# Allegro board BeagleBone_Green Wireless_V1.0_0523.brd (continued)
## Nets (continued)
CAP_VDD_SRAM_MPU: C90.1 U5.D11(CAP_VDD_SRAM_MPU)
CLKOUT2: P2.18(EMU3) P9.41(21) R19.2 R20.1 U22.20(B1)
CLKOUT_SRC: R19.1 U5.D14(EVENT_INTR1/TCLKIN/CLKOUT2/TIME)
DDR_A0: U5.F3(DDR_A0) U12.N3(A0)
DDR_A1: U5.H1(DDR_A1) U12.P7(A1)
DDR_A2: U5.E4(DDR_A2) U12.P3(A2)
DDR_A3: U5.C3(DDR_A3) U12.N2(A3)
DDR_A4: U5.C2(DDR_A4) U12.P8(A4)
DDR_A5: U5.B1(DDR_A5) U12.P2(A5)
DDR_A6: U5.D5(DDR_A6) U12.R8(A6)
DDR_A7: U5.E2(DDR_A7) U12.R2(A7)
DDR_A8: U5.D4(DDR_A8) U12.T8(A8)
DDR_A9: U5.C1(DDR_A9) U12.R3(A9)
DDR_A10: U5.F4(DDR_A10) U12.L7(A10)
DDR_A11: U5.F2(DDR_A11) U12.R7(A11)
DDR_A12: U5.E3(DDR_A12) U12.N7(A12)
DDR_A13: U5.H3(DDR_A13) U12.T3(A13)
DDR_A14: U5.H4(DDR_A14) U12.T7(A14)
DDR_A15: U5.D3(DDR_A15) U12.M7(A15)
DDR_BA0: U5.C4(DDR_BA0) U12.M2(BA0)
DDR_BA1: U5.E1(DDR_BA1) U12.N8(BA1)
DDR_BA2: U5.B3(DDR_BA2) U12.M3(BA2)
DDR_CASN: U5.F1(DDR_CASN) U12.K3(CASN)
DDR_CKE: R96.2 U5.G3(DDR_CKE) U12.K9(CKE)
DDR_CLK: U5.D2(DDR_CK) U12.J7(CK)
DDR_CLKN: U5.D1(DDR_NCK) U12.K7(CKN)
DDR_CSN: U5.H2(DDR_CSN0) U12.L2(CSN)
DDR_D0: U5.M3(DDR_D0) U12.E3(DQ0)
DDR_D1: U5.M4(DDR_D1) U12.F7(DQ1)
DDR_D2: U5.N1(DDR_D2) U12.F2(DQ2)
DDR_D3: U5.N2(DDR_D3) U12.F8(DQ3)
DDR_D4: U5.N3(DDR_D4) U12.H3(DQ4)
DDR_D5: U5.N4(DDR_D5) U12.H8(DQ5)
DDR_D6: U5.P3(DDR_D6) U12.G2(DQ6)
DDR_D7: U5.P4(DDR_D7) U12.H7(DQ7)
DDR_D8: U5.J1(DDR_D8) U12.D7(DQ8)
DDR_D9: U5.K1(DDR_D9) U12.C3(DQ9)
DDR_D10: U5.K2(DDR_D10) U12.C8(DQ10)
DDR_D11: U5.K3(DDR_D11) U12.C2(DQ11)
DDR_D12: U5.K4(DDR_D12) U12.A7(DQ12)
DDR_D13: U5.L3(DDR_D13) U12.A2(DQ13)
DDR_D14: U5.L4(DDR_D14) U12.B8(DQ14)
DDR_D15: U5.M1(DDR_D15) U12.A3(DQ15)
DDR_DQM0: U5.M2(DDR_DQM0) U12.E7(LDM)
DDR_DQM1: U5.J2(DDR_DQM1) U12.D3(UDM)
DDR_DQS0: U5.P1(DDR_DQS0) U12.F3(LDQS)
DDR_DQS1: U5.L1(DDR_DQS1) U12.C7(UDQS)
DDR_DQSN0: U5.P2(DDR_DQSN0) U12.G3(LDQSN)
DDR_DQSN1: U5.L2(DDR_DQSN1) U12.B7(UDQSN)
DDR_ODT: U5.G1(DDR_ODT) U12.K1(ODT)
DDR_RASN: U5.G4(DDR_RASN) U12.J3(RASN)
DDR_RESETN: R97.2 U5.G2(DDR_RESETN) U12.T2(RESET#)
DDR_VREF: C28.1 C123.1 C124.1 R98.2 R100.1 U5.J4(VREFSSTL) U12.H1(VREF_DQ) U12.M8(VREF_CA)
DDR_VTP: R22.2 U5.J3(DDR_VTP)
DDR_WEN: U5.B2(DDR_WEN) U12.L3(WEN)
EHRPWM1A: P9.14(32) U5.U14(GPMC_A2/GMII2_TXD3/RGMII2_TD3/M)
EHRPWM1B: P9.16(33) U5.T14(GPMC_A3/GMII2_TXD2/RGMII2_TD2/M)
EHRPWM2A: P8.19(10) U5.U10(GPMC_AD8/LCD_DATA23/MMC1_DAT0/M)
EHRPWM2B: P8.13(7) U5.T10(GPMC_AD9/LCD_DATA22/MMC1_DAT1/M)
EMMC_RSTN: R111.2 R162.2 U13.K5(R\S\T\)
EMMC_VCCI: C125.1 U13.C2(VCCI)
ENZ_KALDO_1P8V: R54.2 U5.B4(ENZ_KALDO_1P8V)
GPIO0_7: P9.42(46) R50.1 R51.1
GPIO0_7SRC: R50.2 U5.C18(ECAP0_IN_PWM0_OUT/UART3_TXD/SPI)
GPIO0_26: P8.14(32) R187.2 R189.1 U5.T11(GPMC_AD10/LCD_DATA21/MMC1_DAT2/)
GPIO0_27: P8.17(9) U5.U12(GPMC_AD11/LCD_DATA20/MMC1_DAT3/) U22.18(B2)
GPIO1_12: P8.12(31) R206.1 U5.T12(GPMC_AD12/LCD_DATA19/MMC1_DAT4/)
GPIO1_13: P8.11(6) R205.1 U5.R12(GPMC_AD13/LCD_DATA18/MMC1_DAT5/)
GPIO1_14: P8.16(33) R204.1 U5.V13(GPMC_AD14/LCD_DATA17/MMC1_DAT6/)
GPIO1_15: P8.15(8) R203.1 U5.U13(GPMC_AD15/LCD_DATA16/MMC1_DAT7/)
GPIO1_16: P9.15(8) R160.2
GPIO1_17: P9.23(12) U5.V14(GPMC_A1/GMII2_RXDV/RGMII2_RCTL/)
GPIO1_28: P9.12(31) R188.2 R190.1 U5.U18(GPMC_BE1N/GMII2_COL/GPMC_CSN6/M)
GPIO1_29: P8.26(38) R198.1 U5.V6(GPMC_CSN0/GPIO1_29)
GPIO2_0: R161.2 R208.1
GPIO2_1: P8.18(34) R207.1 U5.V12(GPMC_CLK/LCD_MEM_CLK/GPMC_WAIT1)
GPIO3_18: R51.2 U5.B12(MCASP0_ACLKR/EQEP0A_IN/MCASP0_A)
GPIO3_19: P9.27(14) U5.C13(MCASP0_FSR/EQEP0B_IN/MCASP0_AXR)
GPIO3_20: R20.2 U5.D13(MCASP0_AXR1/EQEP0_INDEX//MCASP1)
GPIO3_21: P9.25(13) R167.2 U5.A14(MCASP0_AHCLKX/EQEP0_STROBE/MCAS)
HDMI_INT: R169.1 R170.1 U5.U16(GPMC_A9/GMII2_RXD2/RGMII2_RD2/M)
HDMICLK_DISN: U5.V17(GPMC_A11/GMII2_RXD0/RGMII2_RD0/) Y4.1(OE)
HUB_AVDD: C181.1 C182.1 C185.1 C186.2 C187.1 C188.1 L15.2 R219.1 R220.1 R225.2 U23.5(AVDD#5) U23.9(AVDD#9) U23.14(AVDD#14) U23.28(V33)
HUB_DM1: D11.1 J8.A2(DM_T) U23.3(DM1)
HUB_DM2: D14.2 J8.B2(DM_B) U23.6(DM2)
HUB_DM3: D17.1 J9.A2(DM_T) U23.12(DM3)
HUB_DM4: D20.2 J9.B2(DM_B) U23.15(DM4)
HUB_DP1: D10.1 J8.A3(DP_T) U23.4(DP1)
HUB_DP2: D13.2 J8.B3(DP_B) U23.7(DP2)
HUB_DP3: D16.1 J9.A3(DP_T) U23.13(DP3)
HUB_DP4: D19.2 J9.B3(DP_B) U23.16(DP4)
HUB_RESET#: C199.1 R227.1 R228.2 U23.17(RESET#)
HUB_VBUS: C190.1 C192.1 C194.1 C196.1 C198.1 FB8.2 L17.2 L18.2 L19.2 L20.2 U24.1(OUT)
I2C0_SCL: R3.2 U2.28(SCL) U5.C16(I2C0_SCL/TIMER7/UART2_RTSN/ECAP) U7.1(SCL)
I2C0_SDA: R4.2 U2.27(SDA) U5.C17(I2C0_SDA/TIMER4/UART2_CTSN/ECAP) U7.3(SDA)
I2C1_SCL: P9.17(9) U5.A16(SPI0_CS0/MMC2_SDWP/I2C1_SCL/EHR)
I2C1_SDA: P9.18(34) U5.B16(SPI0_D1/MMC1_SDWP/I2C1_SDA/EHRP)
I2C2_SCL: C202.1 J4.1 P9.19(10) U5.D17(UART1_RTSN/TIMER5/DCAN0_RX/I2C2)
I2C2_SDA: C203.1 J4.2 P9.20(35) U5.D18(UART1_CTSN/TIMER6/DCAN0_TX/I2C2)
JTAG_EMU0: P2.13(EMU0) R23.2 U5.C14(EMU0/GPIO3_7)
JTAG_EMU1: P2.14(EMU1) R24.2 U5.B14(EMU1/GPIO3_8)
JTAG_TCK: P2.9(TCKRTN) P2.11(TCK) U5.A12(TCK)
JTAG_TDI: P2.3(TDI) U5.B11(TDI)
JTAG_TDO: P2.7(TDO) U5.A11(TDO)
JTAG_TMS: P2.1(TMS) U5.C11(TMS)
JTAG_TRSTN: P2.2(TRSTN) R25.1 U5.B10(NTRST)
LCD_DATA0: P8.45(23) R70.2 R95.1 U5.R1(LCD_DATA0/GPMC_A0//EHRPWM2A//PR)
LCD_DATA1: P8.46(48) R69.2 R94.1 U5.R2(LCD_DATA1/GPMC_A1//EHRPWM2B//PR)
LCD_DATA2: P8.43(22) R68.2 R75.1 R93.1 U5.R3(LCD_DATA2/GPMC_A2//EHRPWM2_TRIP)
LCD_DATA3: P8.44(47) R67.2 R92.1 U5.R4(LCD_DATA3/GPMC_A3//EHRPWM2_SYNC)
LCD_DATA4: P8.41(21) R66.2 R91.1 U5.T1(LCD_DATA4/GPMC_A4//EQEP2A_IN//P)
LCD_DATA5: P8.42(46) R65.2 R90.1 U5.T2(LCD_DATA5/GPMC_A5//EQEP2B_IN//P)
LCD_DATA6: P8.39(20) R64.2 R89.1 U5.T3(LCD_DATA6/GPMC_A6/PR1_EDIO_DATA)
LCD_DATA7: P8.40(45) R63.2 R88.1 U5.T4(LCD_DATA7/GPMC_A7/PR1_EDIO_DATA)
LCD_DATA8: P8.37(19) R62.2 R87.1 U5.U1(LCD_DATA8/GPMC_A12/EHRPWM1_TRIP)
LCD_DATA9: P8.38(44) R61.2 R86.1 U5.U2(LCD_DATA9/GPMC_A13/EHRPWM1_SYNC)
LCD_DATA10: P8.36(43) R60.2 R85.1 U5.U3(LCD_DATA10/GPMC_A14/EHRPWM1A/MC)
LCD_DATA11: P8.34(42) R59.2 R84.1 U5.U4(LCD_DATA11/GPMC_A15/EHRPWM1B/MC)
LCD_DATA12: P8.35(18) R58.2 R83.1 U5.V2(LCD_DATA12/GPMC_A16/EQEP1A_IN/M)
LCD_DATA13: P8.33(17) R57.2 R82.1 U5.V3(LCD_DATA13/GPMC_A17/EQEP1B_IN/M)
LCD_DATA14: P8.31(16) R56.2 R81.1 U5.V4(LCD_DATA14/GPMC_A18/EQEP1_INDEX)
LCD_DATA15: P8.32(41) R55.2 R80.1 U5.T5(LCD_DATA15/GPMC_A19/EQEP1_STROB)
LCD_DE: P8.30(40) R48.2
LCD_HSYNC: P8.29(15) R47.2
LCD_PCLK: P8.28(39) R45.2
LCD_VSYNC: P8.27(14) R46.2
LCDDE: R48.1 U5.R6(LCD_AC_BIAS_EN/GPMC_A11//PR1_ED)
LCDPCLK: R45.1 U5.V5(LCD_PCLK/GPMC_A10//PR1_EDIO_DAT)
LCDVHYNC: R47.1 U5.R5(LCD_HSYNC/GPMC_A9//PR1_EDIO_DAT)
LCDVSYNC: R46.1 U5.U5(LCD_VSYNC/GPMC_A8//PR1_EDIO_DAT)
LDO_PGOOD: U2.46(LDO_PGOOD) U5.B5(RTC_PORZN)
LEDAA: D2.2(A) R72.2
LEDAC: D2.1(C) Q1.6(3)
LEDBA: D3.2(A) R73.2
LEDBC: D3.1(C) Q1.3
LEDCA: D4.2(A) R74.2
LEDCC: D4.1(C) Q2.6(3)
LEDDA: D5.2(A) R71.2
LEDDC: D5.1(C) Q2.3
MMC0_CD: P2.19(EMU4) P10.10(CD) R157.1 U5.C15(SPI0_CS1/UART3_RXD/ECAP1_IN_PWM)
MMC0_CLKO: P10.5(CLOCK) R152.2 U5.G17(MMC0_CLK/GPMC_A24/UART3_CTSN/UA)
MMC0_CMD: P10.3(CMD) R151.2 U5.G18(MMC0_CMD/GPMC_A25/UART3_RTSN/UA)
MMC0_DAT0: P10.7(DAT0) R153.2 U5.G16(MMC0_DAT0/GPMC_A23/UART5_RTSN/U)
MMC0_DAT1: P10.8(DAT1) R154.2 U5.G15(MMC0_DAT1/GPMC_A22/UART5_CTSN/U)
MMC0_DAT2: P10.1(DAT2) R150.2 U5.F18(MMC0_DAT2/GPMC_A21/UART4_RTSN/T)
MMC0_DAT3: P10.2(CD/DAT3) R155.2 U5.F17(MMC0_DAT3/GPMC_A20/UART4_CTSN/T)
MMC1_CLK: P8.21(11) R110.2 U5.U9(GPMC_CSN1/GPMC_CLK/MMC1_CLK/PRT) U13.M6(CLK)
MMC1_CMD: P8.20(35) R109.2 U5.V9(GPMC_CSN2/GPMC_BE1N/MMC1_CMD/PR) U13.M5(CMD)
MMC1_DAT0: P8.25(13) R101.2 U5.U7(GPMC_AD0/MMC1_DAT0//////GPIO1_0) U13.A3(DAT0)
MMC1_DAT1: P8.24(37) R102.2 U5.V7(GPMC_AD1/MMC1_DAT1//////GPIO1_1) U13.A4(DAT1)
MMC1_DAT2: P8.5(3) R103.2 U5.R8(GPMC_AD2/MMC1_DAT2//////GPIO1_2) U13.A5(DAT2)
MMC1_DAT3: P8.6(28) R104.2 U5.T8(GPMC_AD3/MMC1_DAT3//////GPIO1_3) U13.B2(DAT3)
MMC1_DAT4: P8.23(12) R105.2 U5.U8(GPMC_AD4/MMC1_DAT4//////GPIO1_4) U13.B3(DAT4)
MMC1_DAT5: P8.22(36) R106.2 U5.V8(GPMC_AD5/MMC1_DAT5//////GPIO1_5) U13.B4(DAT5)
MMC1_DAT6: P8.3(2) R107.2 U5.R9(GPMC_AD6/MMC1_DAT6//////GPIO1_6) U13.B5(DAT6)
MMC1_DAT7: P8.4(27) R108.2 U5.T9(GPMC_AD7/MMC1_DAT7//////GPIO1_7) U13.B6(DAT7)
OSC0_IN: R234.1 U5.V10(OSC0_IN) U17.5(MOD OUT)
OSC0_OUT: R235.1 U5.U11(OSC0_OUT)
OSC1_IN: C21.2 U5.A6(OSC1_IN) Y1.1
OSC1_OUT: C22.2 U5.A4(OSC1_OUT) Y1.4
OVCUR1#: R224.1 U23.25(OVCUR1#)
P_BYPASS: C4.2 U2.47(BYPASS)
P_INT_LDO: C3.2 U2.48(INT_LDO)
P_L1: L1.1 U2.20(L1)
P_L2: L2.1 U2.23(L2)
P_L3: L3.1 U2.31(L3)
PGANG: D6.1(C) R220.2 U23.23(PGANG)
PMIC_INT: R1.2 U2.45(INT) U5.B18(NNMI)
PMIC_PGOOD: U2.26(PGOOD) U5.B15(PORZN) U16.2(A)
PMIC_POWR_EN: U2.9(PWR_EN) U5.C6(PMIC_POWER_EN)
PROC_A15: R18.1 U5.A15(EVENT_INTR0/TIMER4/CLKOUT1/SPI1)
PSELF: R225.1 R226.2 U23.22(PSELF)
PWR_BUT: P9.9(5) S3.2(B1) S3.4(B2) U2.25(PB_IN)
PWR_LEDR: D1.1(C) R12.2
SLOW_CLK: R213.1 U22.1(A1)
SPI1_CS0: P9.28(39) R236.1 U5.C12(MCASP0_AHCLKR/EHRPWM0_SYNCI_O/M)
SPI1_D0: P9.29(15) R238.1 U5.B13(MCASP0_FSX/EHRPWM0B//SPI1_D0/MM)
SPI1_D1: P9.30(40) R237.1 U5.D12(MCASP0_AXR0/EHRPWM0_TRIPZONE_IN)
SPI1_SCLK: P9.31(16) R239.1 U5.A13(MCASP0_ACLKX/EHRPWM0A//SPI1_SCL)
SYS_5V: C7.2 C8.2 C10.2 C13.2 C180.2 L13.1 L16.2 P9.7(4) P9.8(29) R71.1 R72.1 R73.1 R74.1 R227.2 U2.2(VINLDO) U2.7(SYS1) U2.8(SYS2) U2.21(VIN_DCDC1) U2.22(VIN_DCDC2) U2.32(VIN_DCDC3) U2.39(LDO3_IN) U2.42(LDO4_IN) U20.7(AVIN) U20.8(PVIN)
SYS_RESETN: C24.1 C30.1 P2.15(SRST) P9.10(30) R14.2 S1.2(B1) S1.4(B2) U5.A10(NRESET_INOUT) U16.4(Y)
TESTOUT: TP3.1(TP) U5.A3(TESTOUT)
TIMER4: P8.7(4) U5.R7(GPMC_ADVN_ALE/TIMER4/GPIO2_2)
TIMER5: P8.9(5) U5.T6(GPMC_BE0N_CLE/TIMER5/GPIO2_5)
TIMER6: P8.10(30) U5.U6(GPMC_WEN/TIMER6/GPIO2_4)
TIMER7: P8.8(29) U5.T7(GPMC_OEN_REN/TIMER7/EMU4/GPIO2_)
U5_R13: R160.1 U5.R13(GPMC_A0/GMII2_TXEN/RGMII2_TCTL/)
U5_T13: R161.1 U5.T13(GPMC_CSN3/MMC2_CMD/PR1_MDIO_DAT)
UART0_RX: U5.E15(UART0_RXD/SPI1_CS0/DCAN0_TX/I2C) U15.6(1Y)
UART0_TX: U5.E16(UART0_TXD/SPI1_CS1/DCAN0_RX/I2C) U15.5(2A)
UART1_RXD: P9.26(38) U5.D16(UART1_RXD/MMC1_SDWP/DCAN1_TX/I2)
UART1_TXD: P9.24(37) U5.D15(UART1_TXD/MMC2_SDWP/DCAN1_RX/I2)
UART2_RXD: C204.1 J5.1 P9.22(36) U5.A17(SPI0_SCLK/UART2_RXD/I2C2_SDA/EH)
UART2_TXD: C205.1 J5.2 P9.21(11) U5.B17(SPI0_D0/UART2_TXD/I2C2_SCL/EHRP)
UART3_CTSN: R200.1 R210.1 U5.M17(MDIO_DATA/TIMER6/UART5_RXD/UART)
UART3_RTSN: R199.1 R209.1 U5.M18(MDIO_CLK/TIMER5/UART5_TXD/UART3)
UART3_RXD: U5.L17(GMII1_RXD3/UART3_RXD/RGMII1_RD3) U21.14(B6)
UART3_TXD: U5.L16(GMII1_RXD2/UART3_TXD/RGMII1_RD2) U21.15(B5)
UART4_RXD: P9.11(6) U5.T17(GPMC_WAIT0/GM112_CRS/GPMC_CSN4/)
UART4_TXD: P9.13(7) U5.U17(GPMC_WPN/GMII2_RXERR/GPMC_CSN5/)
USB0_DM: D21.2 P4.2(D-) U5.N18(USB0_DM)
USB0_DP: D22.2 P4.3(D+) U5.N17(USB0_DP)
USB0_ID: D23.2 P4.4(ID) U5.P16(USB0_ID)
USB1_DM: U5.R18(USB1_DM) U23.1(DM0)
USB1_DP: U5.R17(USB1_DP) U23.2(DP0)
USB1_DRVVBUS: R221.2 U5.F15(USB1_DRVVBUS/GPIO3_13) U24.4(EN)
USB1_ID: R49.2 U5.P17(USB1_ID)
USB1_OCN: R223.1 R224.2 U5.T16(GPMC_A10/GMII2_RXD1/RGMII2_RD1/) U24.3(NFAULT)
USB1_VBUS: FB8.1 U5.T18(USB1_VBUS)
USB_DC: C1.2 C36.1 C197.1 D24.2 P4.1(VB) R159.1 R168.1 U2.12(USB) U24.6(IN)
USR0: Q1.2(5) R76.1 U5.V15(GPMC_A5/GMII2_TXD0/RGMII2_TD0/R)
USR1: Q1.5 R77.1 U5.U15(GPMC_A6/GMII2_TXCLK/RGMII2_TCLK)
USR2: Q2.2(5) R78.1 U5.T15(GPMC_A7/GMII2_RXCLK/RGMII2_RCLK)
USR3: Q2.5 R79.1 U5.V16(GPMC_A8/GMII2_RXD3/RGMII2_RD3/M)
VDCDC1: L1.2 R6.1 U2.19(VDCDC1)
VIO: R7.2 U2.18(VIO) U16.5(VCC)
VLDO1: R5.1 R7.1 R8.1 U2.3(VLDO1)
VREFP_ADC: C31.1 C32.1 C33.1 R27.2 U5.B9(VREFP)
VRTC: C16.1 C105.1 R5.2 R26.1 U5.D7(VDDS_RTC)
WAKEUP: R26.2 U2.13(WAKEUP) U5.C5(EXT_WAKEUP)
WL_EN: Q4.1(GATE) R187.1 U18.40(WLAN_EN_SOC)
WL_IRQ: R176.1 U22.3(A2)
WL_SDIO_CLK: R182.1 R195.2 U22.8(A7)
WL_SDIO_CMD: R181.1 R196.2 U22.9(A8)
WL_SDIO_D0: R180.1 R194.2 U22.7(A6)
WL_SDIO_D1: R179.1 R193.2 U22.6(A5)
WL_SDIO_D2: R178.1 R192.2 U22.5(A4)
WL_SDIO_D3: R177.1 R191.2 U22.4(A3)
WP: R156.2 TP4.1(TP) U7.5(WP)
XDMA_EVENT_INTR0: P2.17(EMU2) R18.2
XTAL1: C183.1 U23.10(XTAL1) Y5.1
XTAL2: C184.1 U23.11(XTAL2) Y5.3
ZQ: R99.1 U12.L8(ZQ)
N21769115: R75.2 S2.1(A1) S2.3(A2)
N22155575: R159.2 U5.P15(USB0_VBUS)
N22248684: R167.1 Y4.3(CLK)
N22287501: R162.1 U3.4(Y)
N22287555: U3.2(A) U5.R14(GPMC_A4/GMII2_TXD1/RGMII2_TD1/R)
N22420400: TP5.1(TP) U2.4(BAT1) U2.5(BAT2)
N22420444: TP6.1(TP) U2.6(BAT_SENSE)
N22420447: TP7.1(TP) U2.11(TS)
N22488252: TP9.1(TP) U5.E17(UART0_RTSN/UART4_TXD/DCAN1_RX/I)
N22648410: C25.1 R17.1 R234.2 U17.1(XIN/CXIN) Y2.2
N22648422: C26.1 R17.2 R235.2 U17.2(CKOUT) Y2.1
N22649826: R171.2 U17.3(SSON)
N22650321: R172.2 R174.1 U17.6(ADS0)
N22650344: R173.1 R175.2 U17.7(ADS1)
N22699644: R176.2 R233.2 U18.14(WLAN_IRQ)
N22699649: R177.2 U18.13(WL_SDIO_D3)
N22699658: R178.2 U18.12(WL_SDIO_D2)
N22699663: R179.2 U18.11(WL_SDIO_D1)
N22699668: R180.2 U18.10(WL_SDIO_D0)
N22699673: R181.2 U18.6(WL_SDIO_CMD)
N22699720: R182.2 U18.8(WL_SDIO_CLK)
N22699759: R183.2 U18.50(BT_HCI_RTS)
N22699762: R184.2 U18.51(BT_HCI_CTS)
N22699765: R185.2 U18.52(BT_HCI_TX)
N22699768: R186.2 U18.53(BT_HCI_RX)
N22705626: OSC1.3(OUT) R213.2 U18.36(EXT_32K)
N22705631: C167.1 L4.1 OSC1.1(EN) OSC1.4(VDD)
N22709787: TP22.1(TP) U18.43(BT_UART_DBG)
N22709790: TP23.1(TP) U18.42(WL_UART_DBG)
N22711010: C171.1 C200.1 L7.2 L21.2 U18.32(2G4_ANT1_WB)
N22711020: C171.2 J6.1(CENTER) L8.2
N22712983: C172.1 L9.2 U18.18(2G4_ANT2_W)
N22712987: C172.2 J7.1(CENTER) L10.2
N22724780: R197.1 R198.2 U21.10(OE) U22.10(OE)
N22729983: R203.2 U22.17(B3)
N22729986: R204.2 U22.16(B4)
N22729989: R205.2 U22.15(B5)
N22729992: R206.2 U22.14(B6)
N22729995: R207.2 U22.13(B7)
N22729998: R208.2 U22.12(B8)
N22732227: TP14.1(TP) U18.27(GPIO_1)
N22732237: TP15.1(TP) U18.26(GPIO_2)
N22732240: TP16.1(TP) U18.25(GPIO_4)
N22732294: TP17.1(TP) U18.2(GPIO11)
N22732297: TP18.1(TP) U18.3(GPIO9)
N22732316: TP19.1(TP) U18.4(GPIO10)
N22732319: TP20.1(TP) U18.5(GPIO12)
N22732977: C177.2 L13.2 U19.5(EN) U19.7(AVIN) U19.8(PVIN)
N22733304: L11.1 U19.2(SW)
N22733307: R214.2 R215.1 U19.4(FB)
N22764895: L15.1 U23.21(DVDD)
N22765441: L16.1 U23.27(V5)
N22766342: R218.1 U23.8(RREF)
N22767849: TP24.1(TP) U23.26(SDA)
N22767859: TP25.1(TP) U23.18(TEST/SCL)
N22768480: D6.2(A) R219.2
N22769591: C189.1 D9.1 J8.A1(VBUS_T) L19.1
N22769632: C191.1 D12.2 J8.B1(VBUS_B) L20.1
N22770199: C193.1 D15.1 J9.A1(VBUS_T) L17.1
N22770224: C195.1 D18.2 J9.B1(VBUS_B) L18.1
N22776606: R222.2 U24.2(ILIM)
N22780216: D7.2(A) R229.2
N22783783: D8.2(A) R230.2
N22784813: ANT.1(FEED) C200.2 L22.2
N22805505: D7.1(C) Q3.3(DRAIN)
N22805508: D8.1(C) Q4.3(DRAIN)
N22816281: J4.3 R231.1
N22816655: J5.3 R232.1
N22868112: R216.2 R217.1 U20.4(FB)
N22868125: L12.1 U20.2(SW)
N22871921: R200.2 U21.12(B8)
N22871924: R199.2 U21.13(B7)
N22888492: R236.2 U21.16(B4)
N22888495: R239.2 U21.20(B1)
N22888517: R238.2 U21.18(B2)
N22888520: R237.2 U21.17(B3)

Pads without a net: J1 2 3 6; NOREF 1; NOREF#3 1; NOREF#9 1; NOREF#10 1; NOREF#12 1; NOREF#18 1; NOREF#26 1; NOREF#34 1; NOREF#35 1; NOREF#36 1; NOREF#37 1; NOREF#38 1; NOREF#39 1; NOREF#40 1; P2 6; U2 14 15 16 17 33 34 35 36 37 38 44; U3 1; U5 E18 F16 H16 H17 H18 J15 J16 J17 J18 K15 K16 K17 K18 L15 L18 M5 M15 M16 P18; U12 J1 J9 L1 L9; U13 A1 A2 A6 A7 A8 A9 A10 A11 A12 A13 A14 B1 B7 B8 B9 B10 B11 B12 B13 B14 C1 C3 C5 C7 C8 C9 C10 C11 C12 C13 C14 D1 D2 D3 D4 D12 D13 D14 E1 E2 E3 E5 E8 E9 E10 E12 E13 E14 F1 F2 F3 F10 F12 F13 F14 G1 G2 G3 G10 G12 G13 G14 H1 H2 H3 H5 H12 H13 H14 J1 J2 J3 J5 J12 J13 J14 K1 K2 K3 K6 K7 K10 K12 K13 K14 L1 L2 L3 L12 L13 L14 M1 M2 M3 M7 M8 M9 M10 M11 M12 M13 M14 N1 N3 N6 N7 N8 N9 N10 N11 N12 N13 N14 P1 P2 P7 P8 P9 P10 P11 P12 P13 P14; U16 1; U18 21 22 62; U23 19 20 24; Y1 2 3

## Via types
v1: diameter 0.457, hole 0.203, TOP to BOTTOM, 923 vias
v2: diameter 0.559, hole 0.305, TOP to BOTTOM, 34 vias
v3: diameter 0.61, hole 0.305, TOP to BOTTOM, 18 vias

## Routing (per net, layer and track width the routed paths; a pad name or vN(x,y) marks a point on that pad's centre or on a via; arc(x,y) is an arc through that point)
DGND: length 587.9
  TOP w0.076: 27.73,110.05 27.88,110.05 27.89,110.04 28.23,110.04 28.49,109.79 U13.N2
  TOP w0.178: U13.N5 U13.P4
  TOP w0.191: 40.36,102.72 40.13,102.72 39.37,103.48 36.45,103.48 36.2,103.23 ; v1(37.06,102.31) 37.06,102.44
  TOP w0.203: v1(27.41,110.21) 27.57,110.05 27.73,110.05 ; U13.H10 30.99,105.51 31.24,105.26 v1(31.24,105.18) ; U13.P4 26.98,108.79 v1(26.49,109.27) ; v1(31.19,108.81) 31.19,108.59 31.34,108.43 U13.G5 ; U2.30 25.85,80.17 25.65,80.37 v2(25.27,80.37) ; U13.P6 27.57,107.79 v1(27.43,107.65) ; U2.41 v1(24.86,84.75) ; U13.C4 v1(32.99,108.29) ; U13.K8 v1(29.46,106.79) ; v1(32.99,107.11) 32.67,107.11 U13.E7
  TOP w0.254: U5.V1 53.92,101.14 v1(53.92,101.78) ; v1(67.7,93.89) U12.D8 ; U5.F8 v1(47.92,91.94) U5.G9 ; v1(68.5,85.09) U12.P9 ; U12.G9 v1(68.5,91.49) U12.F9 ; U5.N10 v1(46.32,97.54) U5.N11 ; v1(67.7,93.09) U12.E8 ; U5.G8 v1(47.92,92.74) U5.H9 ; U5.K7 U5.J7 v1(49.52,93.54) ; U5.H10 v1(46.32,93.54) U5.J10 ; v1(68.5,83.49) U12.T9 ; U5.L13 v1(44.72,95.94) U5.L12 ; v1(46.32,95.14) U5.K10 ; v1(46.32,95.14) U5.K11 ; v1(46.32,95.14) U5.L10 ; v1(61.3,85.09) U12.P1 ; v1(68.5,86.69) U12.M9 ; v1(44.72,92.74) U5.H12 ; v1(61.3,86.69) U12.M1 ; U12.D1 v1(62.1,93.09) U12.E2 ; v1(48.72,93.54) U5.J8 ; U12.G1 60.71,92.08 60.71,92.43 61.09,92.81 61.58,92.81 U12.E1 v1(62.1,92.29) ; v1(61.3,83.49) U12.T1 ; U5.M9 v1(47.92,96.74) U5.M8 ; v1(48.72,92.74) U5.H8 ; U12.A9 v1(68.5,95.49) U12.B9 ; v1(47.92,95.14) U5.K9 ; U5.M14 v1(43.12,96.74) U5.N14 ; U5.M6 v1(49.52,95.94) U5.M7 ; v1(44.72,91.94) U5.G12 45.28,92.18 45.76,92.18 U5.G11 ; v1(20.8,97.79) 20.32,97.31 R218.2 ; v1(62.1,89.09) U12.J2 ; U5.J6 v1(50.32,93.54) U5.H6 ; v1(67.7,89.09) U12.J8 ; v1(61.3,95.49) U12.B1 ; U5.M12 v1(45.52,95.94) U5.L11 ; U5.H7 v1(49.52,92.74) ; v1(46.32,96.74) U5.M10 ; U5.J11 v1(45.52,93.54) ; v1(47.92,93.54) U5.J9 ; v1(62.9,95.49) U12.B3 ; U5.A1 v1(53.92,86.84) ; U5.A18 v1(39.92,87.13) ; v1(49.52,97.54) U5.N7 ; v1(67.7,91.49) U12.G8
  TOP w0.305: v1(55.27,113.37) 55,113.1 U21.11 ; S1.3 9.42,115.16 ; 9.42,115.16 S1.1 ; 9.42,115.16 9.63,115.37 v1(9.8,115.37) ; S3.3 S3.1 9.5,110.97 9.86,111.33 10.31,111.33 v1(10.37,111.27) ; R12.1 v1(7.32,106.12)
  TOP w0.381: v1(33.55,96.27) 33.27,96.55 C159.2 ; D14.1 v1(19.61,99.67) ; R210.2 52.93,112.73 v1(53.52,113.31) ; C183.2 19.2,96.11 Y5.4 18.97,96.34 18.97,97 18.49,97.49 17.09,97.49 16.66,97.05 16.66,95.4 17.44,94.63 Y5.2 17.59,94.1 18.06,93.62 19.56,93.62 19.6,93.67 19.64,93.67 19.85,93.87 19.85,93.91 19.94,94.01 v1(19.94,94.23) 19.94,94.59 20.19,94.84 C184.2 ; 65.26,108.85 U18.G23 ; C186.1 20.4,92.99 20.4,93.34 20.73,93.68 v1(21.67,93.68) ; C24.2 35.05,72.24 v1(35.69,71.6) 36.07,71.98 C30.2 ; R25.2 37.78,74.21 37.46,73.89 v1(37.46,73.7) ; v1(21.67,86.08) 21.59,86.08 20.7,86.97 D16.2 ; R81.2 49.23,108.89 v3(49.68,108.43) 50.11,108.86 R209.2 ; Q2.1 18.02,108.78 17.81,108.99 v1(17.32,108.99) ; D20.1 v1(16.28,86.97) ; 23.37,108.18 R77.2 23.11,109.58 22.73,109.96 22.73,110.46 v1(22.61,110.59) 22.1,110.59 21.99,110.48 Q1.4 ; Q2.4 19.32,109.76 19.48,109.6 19.84,109.6 v1(19.96,109.47) 20.34,109.09 v1(20.34,109.05) 20.44,109.05 20.69,108.8 Q1.1 ; D17.2 D19.1 v1(18.41,86.18) ; v1(31.5,92.89) 31.11,92.89 31.06,92.94 R226.1 ; 76.2,81.13 v1(76.2,81.18) 76.71,80.67 J4.4 78.9,80.67 v1(79.48,80.09) ; R85.2 53.7,105.14 53.29,105.55 53.29,105.64 v1(53.26,105.66) ; v1(23.49,86.46) 22.86,85.83 22.86,85.45 ; v1(37.46,76.3) 37.46,76.05 C29.2 ; v1(57.94,100.28) 57.94,100.97 R91.2 ; U18.61 62.3,103.6 v1(62.31,103.61) ; Y4.2 v1(32.63,99.68) ; D10.2 v1(19.63,100.56) ; 52.81,105.21 v1(53.26,105.66) ; 52.81,105.21 R83.2 ; 52.81,105.21 52.5,105.51 C175.1 53.09,105.84 v1(53.26,105.66) ; R78.2 R79.2 21.97,105.23 v1(22.48,104.72) ; v1(72.52,80.82) 73.36,80.82 L9.1 ; v1(50.29,105.21) 50.29,105.16 R82.2 ; L10.1 v1(73.53,76.94) ; L21.1 75.62,113.46 76.02,113.46 76.02,113.41 ; v1(47.75,77.71) R165.2 ; 32.77,92.05 v1(31.8,92.05) ; 57.91,77.93 57.89,77.95 C96.1 C155.1 57.02,76.81 57.12,76.81 v1(57.4,76.53) ; 12.2,111.03 12.19,111.04 v1(12.17,111.04) ; R86.2 v1(56.13,105.18) ; D11.2 v1(19.47,101.83) ; U18.1 60.8,100.43 v1(60.6,100.23) ; U16.3 32.28,74.81 v1(32,75.08) ; C18.2 v1(19.68,84.68) ; L22.1 v1(76.58,114.07) 76.58,114.1 ; R90.2 58.04,102.97 57.66,102.59 v1(57.53,102.59) 57.15,102.97 R87.2 ; D13.1 v1(19.71,98.4)
  TOP w0.889: 7.98,91.9 J8.S3 ; J8.S3 10.31,89.57 ; J8.S3 7.98,89.57 ; J8.S3 10.31,91.9 ; 11.26,94.4 J8.B4 ; J8.B4 12.44,93.22 ; J8.B4 11.26,93.22 ; J8.B4 12.44,94.4 ; 7.98,102.71 J8.S4 ; J8.S4 10.31,105.04 ; J8.S4 7.98,105.04 ; J8.S4 10.31,102.71 ; 13.88,94.4 J8.A4 ; J8.A4 15.06,93.22 ; J8.A4 15.06,94.4 ; J8.A4 13.88,93.22 ; J9.S4 10.31,84.27 ; J9.S4 7.98,84.27 ; J9.S4 7.98,86.6 ; J9.S4 10.31,86.6 ; TP1.1 62.23,75.13 ; TP1.1 62.23,76.46 ; TP1.1 60.91,75.13 ; TP1.1 60.91,76.46 ; 13.66,86.6 J9.S1 13.66,84.27 ; J8.S2 15.99,89.57 ; J8.S2 13.66,91.9 ; J8.S2 15.99,91.9 ; J8.S2 13.66,89.57 ; 13.66,102.71 J8.S1 ; J8.S1 15.99,105.04 ; J8.S1 15.99,102.71 ; J8.S1 13.66,105.04
  LYR2_GND w0.889: 13.88,75.96 J9.A4 ; J9.A4 15.06,74.78 ; J9.A4 13.88,74.78 ; J9.A4 15.06,75.96 ; 7.98,91.9 J8.S3 ; J8.S3 10.31,91.9 ; J8.S3 7.98,89.57 ; J8.S3 10.31,89.57 ; 4.06,113.39 P4.9 4.06,114.61 ; 60.91,76.46 TP1.1 ; TP1.1 60.91,75.13 ; TP1.1 62.23,75.13 ; TP1.1 62.23,76.46 ; J8.B4 12.44,93.22 ; J8.B4 12.44,94.4 ; J8.B4 11.26,94.4 ; J8.B4 11.26,93.22 ; J9.B4 12.44,74.78 ; J9.B4 11.26,75.96 ; J9.B4 11.26,74.78 ; J9.B4 12.44,75.96 ; 7.98,84.27 J9.S4 ; J9.S4 7.98,86.6 ; J9.S4 10.31,84.27 ; J9.S4 10.31,86.6 ; 73.76,67.69 P9.43 ; P9.43 73.76,66.37 ; P9.43 75.08,66.37 ; P9.43 75.08,67.69 ; P9.44 75.08,68.91 ; P9.44 73.76,70.23 ; P9.44 75.08,70.23 ; P9.44 73.76,68.91 ; P9.46 77.62,68.91 ; P9.46 76.3,70.23 ; P9.46 77.62,70.23 ; P9.46 76.3,68.91 ; 20.22,114.43 P8.1 ; P8.1 20.22,116.15 ; P8.1 21.95,116.15 ; P8.1 21.95,114.43 ; P9.45 77.62,67.69 ; P9.45 76.3,67.69 ; P9.45 76.3,66.37 ; 20.42,117.17 P8.2 ; P8.2 21.74,118.49 ; P8.2 20.42,118.49 ; P8.2 21.74,117.17 ; 13.66,102.71 J8.S1 ; J8.S1 13.66,105.04 ; J8.S1 15.99,102.71 ; J8.S1 15.99,105.04 ; 13.66,86.6 J9.S1 ; J9.S1 15.99,84.27 ; J9.S1 13.66,84.27 ; J9.S1 15.99,86.6 ; 13.88,94.4 J8.A4 ; J8.A4 15.06,94.4 ; J8.A4 15.06,93.22 ; J8.A4 13.88,93.22 ; P9.2 21.74,68.91 ; P9.2 20.42,70.23 ; P9.2 20.42,68.91 ; P9.2 21.74,70.23 ; 44.81,71.88 J1.1 43.08,71.88 ; 18.01,72.59 TP8.1 ; TP8.1 19.33,73.92 ; TP8.1 19.33,72.59 ; TP8.1 18.01,73.92 ; J9.S3 10.31,73.46 ; J9.S3 7.98,71.13 ; J9.S3 10.31,71.13 ; J9.S3 7.98,73.46 ; 7.98,105.04 J8.S4 ; J8.S4 10.31,105.04 ; J8.S4 7.98,102.71 ; J8.S4 10.31,102.71 ; 13.66,91.9 J8.S2 ; J8.S2 15.99,91.9 ; J8.S2 13.66,89.57 ; J8.S2 15.99,89.57 ; 13.66,71.13 J9.S2 ; J9.S2 15.99,71.13 ; J9.S2 15.99,73.46 ; J9.S2 13.66,73.46 ; 4.06,108.17 P4.8 4.06,106.95 ; 21.95,67.89 P9.1 20.22,67.89
  LYR3 w0.889: J9.S4 10.31,84.27 ; J9.S4 7.98,86.6 ; J9.S4 10.31,86.6 ; J9.S4 7.98,84.27 ; J9.S3 10.31,71.13 ; J9.S3 7.98,73.46 ; J9.S3 7.98,71.13 ; J9.S3 10.31,73.46 ; J8.B4 12.44,93.22 ; J8.B4 11.26,93.22 ; J8.B4 11.26,94.4 ; J8.B4 12.44,94.4 ; 11.26,75.96 J9.B4 12.44,75.96 ; 15.06,75.96 J9.A4 13.88,75.96 ; J8.S3 10.31,91.9 ; J8.S3 7.98,89.57 ; J8.S3 10.31,89.57 ; J8.S3 7.98,91.9 ; J8.S4 10.31,102.71 ; J8.S4 7.98,105.04 ; J8.S4 7.98,102.71 ; J8.S4 10.31,105.04 ; J9.S1 15.99,86.6 ; J9.S1 13.66,86.6 ; J9.S1 15.99,84.27 ; J9.S1 13.66,84.27 ; J8.S2 15.99,89.57 ; J8.S2 15.99,91.9 ; J8.S2 13.66,89.57 ; J8.S2 13.66,91.9 ; 13.88,93.22 J8.A4 ; J8.A4 15.06,94.4 ; J8.A4 15.06,93.22 ; J8.A4 13.88,94.4 ; 13.66,102.71 J8.S1 ; J8.S1 13.66,105.04 ; J8.S1 15.99,102.71 ; J8.S1 15.99,105.04
  LYR5_PWR w0.889: P9.44 75.08,70.23 ; P9.44 73.76,68.91 ; P9.44 75.08,68.91 ; P9.44 73.76,70.23 ; 75.08,67.69 P9.43 73.76,67.69 ; P9.46 77.62,70.23 ; P9.46 76.3,68.91 ; P9.46 77.62,68.91 ; P9.46 76.3,70.23 ; 77.62,67.69 P9.45 76.3,67.69
  BOTTOM w0.121: v1(39.88,98.35) 39.88,98.37 40,98.5 C78.2
  BOTTOM w0.191: v1(46.32,89.54) 46.32,89.42 47.11,88.63 C88.2 ; 70.27,96.81 70.28,96.8
  BOTTOM w0.203: v1(51.12,90.34) 50.83,90.62 50.66,90.62 50.21,91.07 C100.2
  BOTTOM w0.254: v1(41.02,110.82) 41.02,111.05 40.34,111.73 36.22,111.73 35.64,111.15 v1(35.64,107.47) 35.64,107.11 35.69,107.06 v1(35.69,106.55) 35.69,105.87 35.66,105.84 v1(35.66,105.49) 35.66,102.31 36.35,101.63 C69.1 ; C128.2 30.33,107.26 30.25,107.26 29.77,106.79 v1(29.46,106.79) ; P4.6 5.95,114.07 5.07,113.19 5.07,112.99 5.03,112.95 5.03,112.88 v1(4.78,112.62) ; v1(32.99,107.11) 32.54,107.11 32.23,106.81 32.16,106.81 C129.2 ; v1(44.72,92.74) v1(44.72,91.94) 44.02,91.24 C70.1 ; v1(55.88,75.29) 54.61,75.29 54.23,75.67 54.23,76.56 53.48,77.3 U15.4 51.68,77.3 51.43,77.06 51.43,76.05 51.68,75.81 U15.1 ; C127.2 v1(26.8,105.89) ; C155.1 57.15,77.06 57.4,76.81 v1(57.4,76.53)
  BOTTOM w0.305: C99.2 v1(49.52,92.74) ; U20.3 21.32,103.37 21.88,103.37 v1(22.15,103.1) ; v1(22.15,103.1) 22.15,103.15 ; v1(22.15,103.1) 22.4,103.35 U20.6 ; v1(24.99,105.16) 24.99,104.27 C180.1 25.03,104.26 25.66,104.26 v1(25.93,103.99) ; v1(75.45,86.31) 75.43,86.29 U19.3 ; v1(49.52,95.94) C97.2 ; v1(49.52,93.54) 49.23,93.83 C48.2 ; v1(7.11,112.62) 6.57,112.08 P4.5 5.24,112.08 5.06,112.27 5.06,112.3 5.04,112.31 5.04,112.35 v1(4.78,112.62) ; v1(46.32,93.54) 46.98,93.54 C49.2 ; v1(44.72,91.94) 45.41,91.94 C63.2 ; 22.03,102.35 v1(22.12,102.44) 21.79,102.44 21.7,102.35 U20.1 ; 7.39,114.1 7.31,114.18 P4.6 ; v1(55.27,113.37) 55.27,112.65 C57.1 ; v1(50.32,93.54) 50.32,94.23 C98.2 ; v1(23.55,106.02) 23.93,106.02 24.05,106.15 C126.1 ; C60.1 v1(44.72,92.74) ; C73.1 v1(49.52,97.54) 48.83,97.54 C43.2 ; C94.2 v1(45.52,95.94) ; C47.2 47.22,95.14 v1(47.92,95.14) ; v1(47.92,91.94) 47.62,91.64 C72.1 ; C46.2 46.02,94.84 v1(46.32,95.14) ; C50.2 v1(48.72,92.74) ; v1(47.92,96.74) 47.62,97.03 C42.2
  BOTTOM w0.381: C38.2 C45.2 39.2,95.9 38.39,95.9 v1(38.23,95.74) ; C176.1 62.23,105.37 v1(62.12,105.49) ; v1(42.7,103.02) 42.7,103 42.59,102.89 C80.2 ; D21.1 v1(11.25,109.45) ; v3(54.99,110.82) 54.43,111.38 R80.2 ; C174.2 69.75,104.93 69.6,105.08 v1(69.6,105.11) ; C92.2 C105.2 C89.2 C91.2 C90.2 C59.2 ; C92.2 C104.2 v1(50.61,83.54) ; C92.2 v1(49.66,83.65) ; 35.18,85.45 35.18,86.33 C62.1 34.42,86.33 34.42,85.45 ; 35.18,85.45 34.42,85.45 ; 35.18,85.45 C64.2 ; v1(57.53,102.59) 57.28,102.84 C61.1 ; v1(9.09,79.96) 9.4,79.65 9.4,79.22 ; D23.1 v1(14.38,111.61) ; v1(37.46,81.32) P2.16 39.41,81.25 40.75,81.25 40.89,81.11 41.63,81.11 41.93,81.4 41.93,82.89 40.96,83.86 P2.20 ; C173.2 60.83,107.62 61.46,108.24 61.46,108.34 61.94,108.83 Q3.2 ; P4.7 3.38,107.38 P4.8 ; v1(50.61,83.54) 52.27,83.54 52.51,83.79 R54.1 ; v1(50.61,83.54) R164.2 ; P10.9 v1(74.22,99.07) ; C125.2 v1(30.61,113.39) ; v1(38.23,91.94) C54.2 C44.2 ; D12.1 v1(10.16,94.74) ; C118.1 71.5,91.24 v1(71.32,91.06) ; C189.2 6.86,101.4 v1(7.42,101.96) ; v1(53.52,113.31) 53.1,113.31 53.05,113.26 52.97,113.26 52.37,112.66 C75.1 ; C152.2 v1(27.43,88.24) ; v1(14.99,88.47) 14.38,88.47 C193.2 ; C108.2 v1(58.55,94.69) ; C112.2 v1(58.55,85.89) ; v1(63.58,111.07) 63.22,110.72 C170.1 ; v1(71.6,105.08) 71.12,105.56 C167.2 ; C16.2 19.94,84.43 v1(19.68,84.68) ; v1(71.17,95.89) 70.76,96.29 C114.2 ; 66.8,98.27 67.06,98.02 R197.2 ; C168.1 68.76,113.8 68.36,114.2 68.12,114.2 68.12,114.45 68.28,114.6 v1(68.28,114.81) ; R29.1 41.02,104.24 v1(40.64,103.86) ; R22.1 58.46,90.78 v1(58.55,90.69) C110.2 ; C81.2 49.28,102.67 48.74,103.2 48.62,103.2 v1(48.61,103.22) 48.49,103.1 48.49,103 48.39,102.9 C84.2 ; C121.2 v1(71.25,84.29) ; C58.2 C106.2 45.36,102.44 45.85,101.96 45.87,101.96 45.97,101.85 v1(47.09,101.85) 47.12,101.83 C56.1 ; R84.2 57.02,111.43 v3(56.35,110.76) ; D15.2 v1(15.11,87.6) ; C71.1 40.49,102.59 v1(40.94,102.13) ; C69.1 36.78,101.98 37.06,102.26 v1(37.06,102.31) ; 34.42,85.45 v1(34.42,85.45) ; v1(26.8,105.89) C158.2 ; v1(38.23,90.01) 38.23,90.01 38.35,89.89 C82.2 C83.2 C85.2 ; v1(38.15,99.16) 38.4,99.42 38.45,99.42 38.54,99.5 38.6,99.5 R49.1 ; P2.12 P2.10 37.71,77.51 37.46,77.26 v1(37.46,76.3) 37.53,76.24 P2.8 ; P4.9 4.75,114 4.93,114.18 P4.6 ; R88.2 53.75,101.96 v1(53.92,101.78) ; C86.2 38.15,100.74 v1(38.1,100.79) ; R190.2 66.5,109.58 v1(66.04,109.12) 65.96,109.04 65.96,108.83 65.67,108.53 65.56,108.53 Q4.2 65.47,109.03 v1(65.46,109.04) 65.46,109.68 R189.2 ; v1(71.27,90.17) 70.75,90.69 C117.2 ; C107.2 v1(58.55,96.29) ; P10.12 77.84,95.59 ; P2.4 v1(37.46,73.7) ; R96.1 v1(71.25,88.29) ; C77.2 v1(37.97,94.44) ; C111.2 v1(58.55,88.29) ; D9.2 v1(9.14,98.5) ; U3.3 32.73,102.83 33.02,102.54 v1(33.15,102.54) R170.2 ; U24.5 v1(6.22,76.1) ; R100.2 C124.2 v1(64.39,86.33) ; C126.1 24.89,105.26 v1(24.99,105.16) ; P10.6 v1(84.39,96.71) ; 55.3,113.34 v1(55.27,113.37) ; R99.2 70.52,87.09 v1(71.25,87.09) ; P10.13 86.36,110.26 v1(85.57,111.05) ; U7.2 31.31,87.03 30.86,86.59 v1(30.86,85.83) ; C76.1 51.9,102.46 C74.1 51.92,102.87 51.71,103.08 v1(51.71,103.17) ; v1(12.17,111.04) 11.75,111.04 11.43,110.72 D22.1 ; v1(31.19,108.81) 31.19,108.99 30.86,109.32 C130.2 ; v1(50.26,103.11) 50.22,103.07 50.22,102.51 C68.1 ; C119.2 v1(71.37,89.49) ; v1(67.7,89.09) U12.J8 C123.2 ; R221.1 v1(9.14,76.89) ; C191.2 v1(9.14,94.87) ; R30.1 C102.2 ; 73.73,106.27 73.76,106.3 ; C109.2 v1(58.55,92.29) ; C120.2 v1(71.37,85.89) ; C122.1 71.24,81.95 v1(71.25,81.95) ; C113.2 v1(58.55,84.29) ; C28.2 v1(58.55,93.54) ; FB3.2 45.59,79.99 v1(45.59,79.22) 44.83,79.22 v1(44.73,79.32) 44.83,79.43 44.83,79.99 FB3.2
  BOTTOM w0.508: OSC1.2 68.56,109.46 67.87,108.76 v1(67.51,108.76)
  BOTTOM w0.635: C2.1 v1(16.71,78.82)
  BOTTOM w0.762: P9.1 P9.2 ; P9.45 P9.46 ; P8.1 P8.2
  BOTTOM w0.889: 15.06,94.4 J8.A4 13.88,94.4 ; 7.98,105.04 J8.S4 ; J8.S4 7.98,102.71 ; J8.S4 10.31,105.04 ; TP1.1 62.23,75.13 ; TP1.1 60.91,76.46 ; TP1.1 60.91,75.13 ; TP1.1 62.23,76.46 ; 7.98,73.46 J9.S3 ; J9.S3 7.98,71.13 ; J9.S3 10.31,71.13 ; J9.S3 10.31,73.46 ; J8.S2 15.99,91.9 ; J8.S2 13.66,89.57 ; J8.S2 13.66,91.9 ; J8.S2 15.99,89.57 ; 13.66,73.46 J9.S2 ; J9.S2 13.66,71.13 ; J9.S2 15.99,73.46 ; 11.26,94.4 J8.B4 12.44,94.4 ; 15.99,86.6 J9.S1 15.99,84.27 ; 15.06,74.78 J9.A4 13.88,74.78 ; 11.26,74.78 J9.B4 12.44,74.78 ; 10.31,89.57 J8.S3 10.31,91.9
  vias: v1(3.51,79.76) v1(4.67,112.12) v1(5.84,77.7) v1(6.58,77.7) v1(8.03,82.83) v1(8.08,83.57) v1(11.21,108.43) v1(12.93,108.26) v1(13.87,110.87) v1(14.73,110.52) v1(14.71,109.17) v1(19.53,114.58) v1(19.46,89.51) v1(20.4,112.32) v1(20.65,113.56) v1(20.8,89.51) v1(22.1,113.51) v1(22.17,103.99) v1(22.35,72.36) v1(22.61,108.18) v1(22.99,72.36) v1(23.22,112.01) v1(23.7,113.31) v1(25.4,90.38) v1(25.91,88.47) v1(25.87,87.06) v1(26.04,90.42) v1(27.33,106.53) v1(27.75,72.24) v1(28.38,72.24) v1(29.21,101.12) v1(29.97,67.26) v1(31.75,93.83) v1(31.75,91.29) v1(32.46,67.21) v1(32.77,94.84) v1(33.63,94.89) v1(35.64,79.53) v1(35.74,81.56) v1(35.74,80.59) v1(35.66,78.47) v1(40.08,101.73) v1(42.27,95.96) v1(45.8,109.32) v1(54.23,83.54) v1(56.77,81.89) v1(62.22,109.61) v1(62.78,109.63) v1(62.87,106.5) v1(63.14,74.78) v1(63.37,76.48) v1(64.01,99.67) v1(64.57,80.95) v1(66.24,98.5) v1(66.62,106.48) v1(66.7,75.49) v1(66.9,81) v1(66.85,76.52) v1(67.21,106.5) v1(68.63,74.98) v1(70.1,83.54) v1(70.23,95.28) v1(71.09,93.22) v1(71.6,111.2) v1(72.46,101.53) v1(72.9,71.35) v1(73.41,113.59) v1(73.79,75.97) v1(73.81,74.98) v1(73.94,85.75) v1(73.86,85.17) v1(73.89,84.53) v1(74.12,99.82) v1(74.17,109.32) v1(74.24,96.22) v1(74.22,94.49) v1(74.35,112.37) v1(74.27,98.07) v1(74.37,102.18) v1(74.65,108.2) v1(74.8,112.01) v1(74.85,113.18) v1(75.16,102.29) v1(75.34,94.72) v1(75.31,77.37) v1(75.39,101.19) v1(75.39,99.01) v1(75.39,96.85) v1(75.36,92) v1(75.44,84.56) v1(75.54,100.13) v1(75.46,97.92) v1(75.69,107.65) v1(76.07,113.56) v1(76.07,77.44) v1(76.2,71.35) v1(76.25,72.54) v1(76.38,88.98) v1(76.45,90.93) v1(76.45,89.97) v1(76.63,107.65) v1(76.66,109.22) v1(76.73,85.57) v1(77.19,113.21) v1(77.24,111.94) v1(77.44,109.88) v1(77.39,85.65) v1(77.47,109.04) v1(77.62,77.62) v1(77.65,72.49) v1(77.93,79.93) v1(78.03,113.94) v1(78.08,110.57) v1(78.11,106.35) v1(78.18,107.34) v1(78.33,76.89) v1(78.36,108.94) v1(78.41,75.62) v1(78.61,116.18) v1(78.66,114.58) v1(78.92,109.68) v1(78.87,94.46) v1(79.15,107.39) v1(79.5,116.43) v1(79.73,109.02) v1(80.01,117.2) v1(80.21,81.84) v1(80.49,106.38) v1(80.9,81.38) v1(81.03,103.99) v1(81.43,109.04) v1(81.56,106.93) v1(81.74,86.92) v1(82.65,93.24) v1(82.83,88.24) v1(82.93,97.89) v1(82.96,89.76) v1(83.08,90.75) v1(83.19,100.56) v1(83.77,111.02) v1(84.68,111.05) v1(84.96,102.36) v1(84.96,100.61) v1(84.99,98.48) v1(85.39,112.75) v1(85.73,111.86) v1(85.73,91.03) v1(85.73,82.37) v1(85.78,84.84) v1(85.93,87.43) v2(3.43,102.49) v2(3.38,101.5) v2(3.48,104.98) v2(3.53,89.84) v2(3.56,100.05) v2(3.63,96.44) v2(3.63,92.51) v2(3.56,90.96) v2(3.71,86.74) v2(3.71,85.73) v2(3.76,84.71) v2(22.48,80.75) v2(22.73,78.71) v2(24,80.37) v2(24,79.1) v3(24.38,96.37) v3(24.38,95.1) v3(24.38,93.83) v3(25.65,96.37) v3(25.65,95.1) v3(25.65,93.83) v3(26.92,96.37) v3(26.92,95.1) v3(26.92,93.83) v3(55.14,109.42) v3(56.34,109.4) v3(65.82,103.42) v3(65.82,101.92) v3(67.02,103.42) v3(67.02,101.92)
GND_EARTH: length 105.4
  TOP w0.889: 14.31,114.87 MTG3.1 ; MTG3.1 17.7,118.26 ; MTG3.1 14.31,118.26 ; MTG3.1 17.7,114.87 ; 14.31,70 MTG1.1 ; MTG1.1 17.7,66.61 ; MTG1.1 14.31,66.61 ; MTG1.1 17.7,70 ; 80.35,69.78 MTG4.1 ; MTG4.1 80.35,73.17 ; MTG4.1 83.74,73.17
  LYR3 w0.889: 14.31,70 MTG1.1 ; MTG1.1 17.7,66.61 ; MTG1.1 14.31,66.61 ; MTG1.1 17.7,70 ; 14.31,114.87 MTG3.1 ; MTG3.1 17.7,114.87 ; MTG3.1 17.7,118.26 ; MTG3.1 14.31,118.26 ; MTG4.1 83.74,73.17 ; MTG4.1 80.35,73.17 ; MTG4.1 80.35,69.78
  LYR4 w0.889: 14.31,118.26 MTG3.1 ; MTG3.1 17.7,114.87 ; MTG3.1 14.31,114.87 ; MTG3.1 17.7,118.26 ; 80.35,69.78 MTG4.1 ; MTG4.1 80.35,73.17 ; MTG4.1 83.74,73.17 ; MTG1.1 17.7,66.61 ; MTG1.1 14.31,66.61 ; MTG1.1 17.7,70 ; MTG1.1 14.31,70
  BOTTOM w0.889: MTG3.1 17.7,114.87 ; MTG3.1 14.31,118.26 ; MTG3.1 14.31,114.87 ; MTG3.1 17.7,118.26 ; MTG1.1 17.7,66.61 ; MTG1.1 14.31,70 ; MTG1.1 14.31,66.61 ; MTG1.1 17.7,70 ; 80.35,73.17 MTG4.1 ; MTG4.1 83.74,73.17 ; MTG4.1 80.35,69.78
  vias: v1(2.59,110.74) v1(2.84,115.11) v1(8.97,67.46) v1(86,99.75) v1(86.31,102.03)
GND_OSC0: length 9
  TOP w0.381: U5.V11 45.92,102.24 45.59,102.57 45.59,104.34 v2(45.49,104.44)
  BOTTOM w0.381: v2(45.49,104.44) 45.85,104.8 R173.2 46.48,105.13 47.19,105.84 47.19,107.37 46.76,107.8 R174.2
GND_OSC1: length 7.3
  TOP w0.254: U5.A5 50.72,87.31 51.43,86.59
  BOTTOM w0.381: v1(51.31,80.11) 51.88,80.68 C21.1 52.51,80.81 ; C22.1 52.51,80.81 ; C22.1 v1(53.15,79.98) ; C22.1 R30.2 ; 52.51,80.81 v1(52.51,82.91)
GNDA_ADC: length 46.4
  TOP w0.254: v1(48.72,90.34) U5.E8
  TOP w0.305: 47.52,87.1 U5.A9
  TOP w0.381: C93.2 C33.2 C31.2 C32.2 ; C93.2 v1(46.48,81.64) ; C93.2 47.24,82.4 47.88,83.03 47.88,86.72 47.52,87.08 47.52,87.1
  LYR4 w0.381: P9.34 60.64,68.49 58.73,68.49 57.91,69.31 57.91,69.95 55.35,72.51 55.35,73.03 54.08,74.3 51.16,74.3 48.44,77.01 48.44,79.78 46.58,81.64 v1(46.48,81.64) 46.48,84.05 47.88,85.45 47.88,87.73 47.24,88.37 47.24,89.89 47.69,90.34 v1(48.72,90.34)
  BOTTOM w0.381: FB3.1 46.23,82.27 46.48,82.02 v1(46.48,81.64)
VDD_1V8: length 15.7
  TOP w0.203: 25.67,84.94 25.22,84.48 25.22,83.99 25.26,83.95 U2.40
  TOP w0.254: v1(41.48,99.11) 41.54,99.11 U5.R16 ; v1(46.32,90.34) U5.D10 U5.E9 ; v1(41.52,97.54) U5.N16
  BOTTOM w0.305: C88.1 47.01,89.64 v1(46.32,90.34) ; C86.1 40.23,100.74 40.99,99.98 40.99,99.78 41.15,99.61 41.15,99.43 v1(41.48,99.11)
  BOTTOM w0.381: v1(26.39,84.79) 26.39,84.84 25.78,85.45 R9.2 ; 46.74,79.76 46.48,79.5 46.48,79.27 46.46,79.25 v1(46.46,79.22) 46.49,79.18 v1(47.28,79.18) 47.37,79.18 47.75,79.57 FB2.2 47.14,79.76 46.74,79.76
  vias: v1(30.3,88.6) v1(30.94,88.62) v1(35.46,96.9) v1(35.51,96.11) v1(38.1,98.45)
VDD_1V8_WIFI: length 45.1
  TOP w0.254: v1(58.17,107.67) 58.17,108.03 57.99,108.21 U21.2
  TOP w0.381: v1(69.62,111.63) 69.62,111.71 69.54,111.79 U18.38 ; R191.1 R192.1 71.96,95.68 71.96,95.17 72.14,95 72.14,94.72 ; 72.14,94.72 73.03,94.72 v1(73.05,94.74) ; 72.14,94.72 72.14,91.67 ; v1(73.66,97.21) 73.53,97.33 73.53,97.41 R233.1
  LYR3 w0.508: v1(72.21,102.69) 72.26,102.74 v1(72.26,103.23) 72.26,107.44 72.42,107.59 v1(72.42,108.08)
  LYR4 w0.508: v1(60.62,108.27) 62.39,108.27 62.83,107.82 68.74,107.82 69.33,108.42 72.07,108.42 v1(72.42,108.08)
  BOTTOM w0.254: C174.1 69.62,103.43 69.14,103.91 69.14,104.17 68.84,104.47 U22.2
  BOTTOM w0.381: v1(60.62,108.27) 59.82,107.47 C173.1 58.95,106.88 v1(58.17,107.67) ; L4.2 70.83,102.84 70.33,102.84 C174.1 ; R214.1 75.44,89.61 75.03,90.02 74.12,90.02 ; v1(69.62,111.63) 69.77,111.63 70.54,112.4 C168.2
  BOTTOM w0.508: C168.2 71.65,112.85 72.61,111.9 72.61,109.74 72.01,109.15 72.01,108.48 v1(72.42,108.08)
VDD_3V3_WIFI: length 37.6
  TOP w0.254: 52.91,107.37 52.91,107.87 53.24,108.21 U21.19
  TOP w0.381: v1(53.85,107.71) 53.5,107.37 52.91,107.37 C175.2 ; R229.1 R230.1 73.28,86.91 73.05,86.68 73.05,86.03 72.93,85.91 72.93,85.33 72.59,84.99 v1(72.09,84.99)
  LYR4 w0.508: v1(72.09,84.99) 72.09,100.99 68.81,104.27 64.14,104.27 v1(62.74,105.66)
  BOTTOM w0.254: U22.19 64.29,104.47 64.14,104.62 64.14,104.75 63.88,105 63.25,105
  BOTTOM w0.381: v1(62.74,105.66) 62.87,105.66 63.25,105.28 63.25,105
  vias: v1(59.54,109.25) v1(63.25,113.46) v1(63.8,113.59) v2(60.6,108.94)
VDD_3V3A: length 106.9
  TOP w0.203: v1(23.76,84.75) 23.76,84.23 24.06,83.93 U2.43
  TOP w0.254: U5.P13 v1(43.92,98.34) ; U5.J14 v1(43.12,93.54) U5.H14 ; U5.K14 v1(43.92,95.14) U5.L14 ; U5.P10 v1(46.32,98.34) U5.P11 ; U5.N5 v1(51.12,96.74) ; U5.G14 v1(43.12,91.94) U5.F14 ; U5.P12 v1(44.72,98.34) ; v1(42.3,99.15) U5.R15 ; U5.P5 v1(51.12,98.34) ; v1(49.52,98.34) U5.P7 U5.P8 ; U5.P6 v1(50.32,98.34) ; v1(42.32,97.54) U5.N15 ; U5.E13 v1(44.72,90.34) U5.E12 v1(45.52,90.34) U5.E11 v1(46.32,91.14) U5.E10
  TOP w0.381: R60.1 54.92,104.8 55.09,104.64 55.11,104.64 55.24,104.5 R61.1 55.37,105.07 v1(55.3,105.14) 56.35,106.2 56.95,106.2 R62.1 R65.1 R66.1 ; v1(36.25,77.04) 35.53,76.32 35.53,76.21 35.05,75.73 R14.1 ; R56.1 R57.1 R58.1 51.32,107.01 51.49,107.01 v1(51.81,107.34) ; R1.1 25.02,85.7 25.7,86.39 v1(25.7,86.46) ; Y4.4 33.54,97.83 34.21,97.16 34.21,96.98 C159.1 v1(34.29,96.29)
  LYR3 w0.381: v1(23.76,84.75) 23.62,84.62 23.62,84.33 22.91,83.62 18.85,83.62 18.44,83.21 v1(18.26,83.21)
  LYR4 w0.305: v1(24.13,105.27) 24.13,105.41 24.44,105.71 25.6,105.71 26.44,104.88 v1(27.13,104.88)
  BOTTOM w0.254: U17.8 43.42,106.67 43.12,106.37 v1(42.71,106.37)
  BOTTOM w0.305: v1(24.13,105.27) 23.86,105 23.86,104.2 23.51,103.85 U20.5 ; C56.2 47.01,99.03 v1(46.32,98.34) ; C158.1 v1(27.13,104.88) ; C66.1 44.02,95.78 44.02,95.24 v1(43.92,95.14) ; v1(46.32,91.14) 46.82,90.63 C72.2 ; C70.2 43.12,91.24 v1(43.12,91.94) 43.12,92.63 C60.2 43.12,92.84 v1(43.12,93.54)
  BOTTOM w0.381: 55.65,102.21 R63.1 R68.1 R64.1 ; 55.65,102.21 55.67,102.23 56.75,102.23 R70.1 R69.1 ; 55.65,102.21 55.65,102.74 C61.2 R67.1 55.75,104.06 55.3,104.52 v1(55.3,105.14) ; R171.1 40.64,109.32 40.56,109.4 v1(40.54,109.4) ; 28.38,86.53 C152.1 R156.1 ; 28.38,86.53 v1(28.38,88.24) ; 28.38,86.53 28.77,86.53 29.21,86.08 U7.4 ; v1(39.37,101.96) 39.24,102.08 C71.2 ; 53.78,110.11 53.78,109.3 v1(51.81,107.34) ; 53.78,110.11 53.78,110.54 ; 53.78,110.11 55.24,110.11 55.75,110.62 55.75,111.09 55.3,111.54 C57.2 R59.1 ; R175.1 R172.1 v1(46.58,106.91) ; 53.78,110.54 53.79,110.54 ; 53.78,110.54 53.78,111.16 53.39,111.54 R55.1 C75.2 ; U3.5 28.81,104.13 28.07,104.88 C158.1 27.69,102.67 28.6,101.75 29.79,101.75 R169.2 29.84,102.01 v1(30.35,102.51) ; C73.2 51.23,96.84 v1(51.12,96.74) ; 9.4,78.08 9.96,78.08 11.35,76.68 15.32,76.68 15.7,77.06 15.7,79.02 16.64,79.96 16.64,82.55 17.3,83.21 v1(18.26,83.21) ; R156.1 26.54,86.46 26.54,85.7 27.18,85.06 27.18,84.43 26.8,84.05 C37.1 R3.1 28.45,84.3 R4.1 v1(28.83,83.64) ; R156.1 25.77,86.53 v1(25.7,86.46) ; C69.2 36.45,100.61 v1(36.14,100.91) ; v1(23.76,84.75) 23.76,84.44 23.37,84.05 C15.2 ; C59.1 v1(44.89,86.08)
VDD_3V3AUX: length 35.5
  TOP w0.203: 20.6,82.95 20.98,82.57 U2.1
  TOP w0.254: D1.2 7.05,107.42 8.5,105.97 v1(10.36,105.97)
  TOP w0.381: v1(20.55,86.08) 20.57,86.06 20.57,86 20.7,85.88 C18.1 20.7,85.04 20.6,84.94 20.6,82.95
  LYR4 w0.254: v1(10.36,105.97) 12.07,105.97 12.37,105.67 12.37,105.66 13.03,105 13.03,89.54 13.61,88.95 16.56,88.95 19.43,86.08 v1(20.55,86.08)
VDD_3V3B: length 124.3
  TOP w0.203: v1(31.75,108.81) 31.99,108.57 U13.F5 ; v1(30.32,105.21) 30.33,105.22 30.33,105.36 30.49,105.52 U13.J10 ; U13.E6 32.6,107.68 v1(32.99,107.68) 33,107.68 33.11,107.79 U13.C6 ; v1(29.46,105.94) 29.46,105.95 29.46,105.96 29.46,106.05 29.7,106.29 U13.K9 ; v1(27.38,109.29) U13.P3 U13.N4 ; U13.M4 v1(29.46,108.79) ; v1(26.9,108.33) 27.23,108.33 27.27,108.29 U13.P5
  TOP w0.381: v2(80.52,91.03) 81.03,91.54 v2(83.95,91.54) ; v1(36.09,75.01) 36.45,74.65 36.83,74.65 C29.1 37.21,74.52 38.86,76.17 38.86,77.76 38.61,78.02 R23.1 38.23,79.22
  LYR3 w0.381: v1(56.77,75.29) 56.13,74.65 55.43,74.65 54.97,75.11 49.59,75.11 49.58,75.12 47.6,75.12 46.92,75.8 43.07,75.8 43.03,75.76 43.02,75.76 42.04,74.78 41.02,74.78 40.83,74.97 36.64,74.97 36.59,75.01 v1(36.09,75.01)
  LYR3 w0.635: v2(80.01,93.57) 81.15,94.72 81.15,100.66 85.45,104.95 85.45,108.89 v1(85.42,108.92)
  LYR4 w0.381: v1(56.77,75.29) 56.77,77.19 55.75,78.21 v1(55.75,79.36)
  LYR4 w0.508: v2(83.82,82.02) 83.82,86.08 80.52,89.38 v2(80.52,91.03)
  LYR5_PWR w0.889: 24.28,67.69 P9.3 22.96,67.69 ; 22.96,70.23 P9.4 ; P9.4 24.28,68.91 ; P9.4 24.28,70.23 ; P9.4 22.96,68.91
  BOTTOM w0.254: v1(31.75,108.81) 31.75,108.32 31.88,108.19 C129.1 32.27,107.54 32.4,107.68 v1(32.99,107.68) ; v1(26.9,108.33) 26.8,108.23 C127.1 ; U15.8 56.53,75.81 C155.2 56.51,76.31 U15.7 ; v1(30.32,105.21) 30.33,105.22 30.33,105.36 30.49,105.52 30.49,105.77 30.61,105.88 C128.1 30.21,106.53 29.97,106.29 29.72,106.29 29.46,106.03 29.46,105.95 v1(29.46,105.94)
  BOTTOM w0.381: v1(55.75,79.36) 55.74,79.35 49.66,79.35 49.34,79.67 R163.1 ; C126.2 v1(24.89,108.89) ; C130.1 31.88,108.94 v1(31.75,108.81) ; R111.1 29.44,108.81 v1(29.46,108.79) ; 80.52,92.18 80.39,92.3 R151.1 R155.1 R150.1 R157.2 ; v1(36.09,75.01) 35.97,75.01 35.93,74.97 P2.5 ; P10.4 85.09,109.24 v1(85.42,108.92) ; R154.1 R153.1 ; R153.1 R152.1 ; R153.1 84.46,92.05 v2(83.95,91.54) ; R101.1 R102.1 v1(47.24,111.73) R105.1 R106.1 R110.1 R109.1 v1(42.77,111.73) ; R104.1 v1(28.7,110.85) ; R103.1 v1(27.43,110.85) ; C155.2 v1(56.77,75.29) ; R107.1 v1(24.89,110.85) ; R108.1 v1(26.16,110.85)
  BOTTOM w0.508: C154.1 80.9,93.95 81,94.05 81,94.18 81.15,94.34 R232.2 ; C154.1 v2(80.01,93.57) ; C154.1 80.9,92.56 80.52,92.18 v2(80.52,91.03) ; R231.2 83.95,82.14 v2(83.82,82.02) ; 58,113.51 57.96,113.51
  BOTTOM w0.762: P9.3 P9.4
  vias: v1(17.63,106.73) v1(18.04,106.29) v1(18.16,106.73) v1(57.42,113.67) v1(57.81,114.02)
VDD_5V: length 6.5
  TOP w0.203: U2.10 20.32,78.97
  LYR4 w0.889: P9.6 26.82,68.91 ; P9.6 25.5,70.23 ; P9.6 26.82,70.23 ; P9.6 25.5,68.91 ; 26.82,67.69 P9.5 25.5,67.69
  vias: v1(18.29,76.94) v1(19.43,78.21) v1(19.43,77.5)
VDD_ADC: length 33.1
  TOP w0.254: v1(48.72,89.54) U5.D8
  TOP w0.381: v1(47.24,86.08) 47.24,86.07 47.24,85.22 R27.1 46.48,84.46 C93.1 47.12,83.41 v1(47.24,83.54)
  LYR3 w0.381: v1(47.24,86.08) 47.24,89.76 47.62,90.14 48.11,90.14 v1(48.72,89.54)
  LYR4 w0.381: v1(47.24,83.54) 47.24,82.3 49,80.54 49,77.22 51.36,74.85 54.48,74.85 55.47,73.86 57.05,73.86 58.55,72.37 58.55,70.21 P9.32
  BOTTOM w0.381: FB2.1 47.75,82.27 47.24,82.78 v1(47.24,83.54)
VDD_CORE: length 28.3
  TOP w0.254: U5.H11 v1(45.52,92.74) ; U5.M11 v1(46.32,95.94) ; U5.N12 v1(44.72,96.74) U5.N13 ; U5.K6 v1(50.32,95.14) U5.L6 ; v1(49.52,91.94) U5.G7 ; U5.N9 v1(47.92,97.54) U5.N8 ; U5.F6 v1(50.32,91.94) U5.G6 ; U5.F7 v1(49.52,91.14) ; U5.G10 v1(46.32,92.74) ; v1(48.72,95.94) U5.L8 ; U5.J12 v1(44.72,93.54) ; U5.K12 v1(45.52,95.14) ; U5.L7 v1(48.72,95.14) U5.K8 ; v1(47.92,95.94) U5.L9 ; U5.M13 v1(43.92,96.74)
  BOTTOM w0.305: v1(41.52,95.94) 40.34,95.94 C45.1 ; v1(45.52,95.14) 45.01,94.63 C46.1 45.01,93.83 v1(44.72,93.54) v1(45.52,92.74) ; C41.1 43.92,97.43 v1(43.92,96.74) v1(44.72,96.74) ; C42.1 47.22,97.94 47.52,97.94 v1(47.92,97.54) ; C48.1 48.32,94.44 U5.K8 v1(48.72,95.14) v1(50.32,95.14) ; C43.1 v1(48.72,95.94) ; C50.1 48.83,91.14 v1(49.52,91.14) v1(49.52,91.94) v1(50.32,91.94) ; v1(47.92,95.94) 47.23,95.94 C47.1 47.01,95.94 v1(46.32,95.94) ; v1(46.32,92.74) 46.42,92.63 C49.1
  BOTTOM w0.381: v1(40.72,91.94) C54.1 C44.1
  vias: v1(31.34,81.15) v1(31.34,79.86) v1(31.34,78.99) v1(31.52,82.22) v1(32,81.15) v1(32.03,78.97) v1(32.08,79.86) v1(33.71,90.63) v1(33.78,89.92) v1(34.52,90.83) v1(34.47,90.02) v1(36.96,92.49) v1(36.96,91.73)
VDD_MPU: length 29.6
  TOP w0.254: U5.J13 v1(43.92,93.54) U5.H13 44.21,93.03 44.21,92.44 U5.G13 v1(43.92,91.94) U5.F13 v1(44.72,91.14) U5.F12 U5.F11 45.98,91.6 46.65,91.6 U5.F10
  TOP w0.635: 36.8,86.69 36.18,86.06 36.18,83.71 36.22,83.66 36.22,83.61 36.73,83.1 36.73,80.4 36.5,80.16 36.5,78.36 34.57,76.43 31.11,76.43 ; 30.48,75.64 30.48,75.79 31.11,76.43 ; 31.11,76.43 30.4,76.43 30.07,76.1
  BOTTOM w0.305: C63.1 44.82,91.03 v1(44.72,91.14)
  BOTTOM w0.381: v1(43.92,93.54) 44.02,93.64 C65.1 ; C62.2 36.58,86.97 36.83,87.22 v1(37.48,87.22) v1(37.48,86.59) 36.7,86.59 C62.2 ; C62.2 36.2,86.33 C64.1
  vias: v1(27.88,75.03) v1(28.51,75.03)
VDD_MPUON: length 10.6
  TOP w0.121: TP2.1 57.66,80.68 56.97,81.38 56.39,81.38 55.88,81.89 55.88,82.78 54.61,84.05 54.1,84.05 53.72,84.43 53.72,85.19 53.12,85.8 U5.A2
VDD_PLL: length 12.5
  TOP w0.254: U5.R10 46.72,98.75 v1(46.32,99.14) U5.R11 v1(45.52,98.34) ; U5.H15 v1(42.32,92.74) ; v1(49.52,90.34) U5.E7
  LYR3 w0.381: v1(38.23,96.96) 40.14,96.96 40.19,97.01 42.54,97.01 42.61,97.08 42.62,97.08 43.05,97.51 44.69,97.51 v1(45.52,98.34) v1(46.32,99.14)
  BOTTOM w0.305: C94.1 v1(45.52,98.34)
VDD_RTC: length 5.4
  TOP w0.254: v1(50.32,89.54) U5.D6
  BOTTOM w0.121: C104.1 50.15,85.78 50.15,87.42 50.72,87.99 50.72,88.66 50.72,89.13 v1(50.32,89.54)
VDDS: length 42
  TOP w0.254: U5.N6 v1(49.52,96.74) ; v1(43.12,98.34) U5.P14 ; v1(47.92,91.14) U5.F9 ; U5.E14 v1(43.12,90.34) ; v1(47.92,98.34) U5.P9 ; v1(44.72,95.14) U5.K13 ; U5.E6 v1(50.32,90.34)
  LYR5_PWR w0.305: v1(44.72,95.14) 45.26,94.59 46.86,94.59 v1(47.12,94.34)
  BOTTOM w0.121: 42.72,100.39 42.72,98.74
  BOTTOM w0.254: 42.72,98.74 v1(43.12,98.34)
  BOTTOM w0.305: 42.72,100.39 42.83,100.5 42.83,101.22
  BOTTOM w0.381: R9.1 R8.2 21.08,85.57 21.08,87.48 22.78,89.18 33.35,89.18 33.99,88.54 37.29,88.54 39.23,86.6 40.28,86.6 40.64,86.97 40.64,87.86 ; C80.1 42.83,101.22 42.93,101.22 43.31,101.6 43.31,102.86 43.53,103.08 45.5,103.08 45.69,102.89 45.69,102.88 45.78,102.78 45.78,102.75 46.09,102.44 46.12,102.44 46.15,102.41 46.51,102.41 46.52,102.41 46.96,102.41 46.96,102.41 47.37,102.41
VDDS_DDR: length 52.1
  TOP w0.254: v1(62.1,95.49) U12.B2 ; U5.E5 U5.F5 v1(51.12,91.94) U5.G5 ; v1(68.5,85.89) U12.N9 ; v1(61.3,96.29) U12.A1 ; v1(61.3,92.29) U12.F1 ; v1(68.5,94.69) U12.C9 ; v1(62.1,88.29) U12.K2 ; v1(61.3,94.69) U12.C1 ; U5.K5 v1(51.12,95.14) U5.L5 ; v1(68.5,93.09) U12.E9 ; v1(68.5,93.89) U12.D9 ; v1(61.3,84.29) U12.R1 ; v1(68.5,84.29) U12.R9 ; v1(67.7,96.29) U12.A8 ; U5.J5 v1(51.12,93.54) U5.H5 ; v1(68.5,90.69) U12.H9 ; v1(67.7,88.29) U12.K8 ; v1(62.9,93.09) U12.D2 ; v1(61.3,85.89) U12.N1 ; v1(66.9,91.49) U12.G7
  TOP w0.305: v1(62.1,90.69) U12.H2
  TOP w0.381: C96.2 v1(56.77,80.94)
  BOTTOM w0.305: C97.1 51.12,95.83 v1(51.12,95.14) 51.12,94.44 C98.1 51.12,94.23 v1(51.12,93.54) 51.12,92.84 C99.1 51.12,92.63 v1(51.12,91.94) 51.12,91.24 C100.1
  BOTTOM w0.381: v1(68.5,94.69) C115.1 ; v1(68.5,85.89) C120.1 ; v1(67.7,88.29) 68.9,89.49 C119.1 ; v1(61.3,85.89) C112.1 ; C110.1 60.55,90.69 61.08,91.22 61.52,91.22 61.53,91.21 61.58,91.21 v1(62.1,90.69) ; C101.1 53.59,85.45 v1(54.23,85.45) ; v1(61.3,94.69) C108.1 ; v1(68.5,84.29) C121.1 ; v1(68.5,93.89) 68.69,93.7 C116.1 ; C107.1 v1(61.3,96.29) ; v1(68.5,93.09) 68.5,92.51 68.83,92.18 C118.2 69.72,92 69.37,91.64 69.37,90.79 C117.1 v1(68.5,90.69) ; C109.1 v1(61.3,92.29) ; v1(66.9,91.49) 66.1,90.69 R98.1 ; C122.2 v1(67.44,81.95) ; v1(62.1,88.29) 61.54,87.73 60.88,87.73 C111.1 ; C114.1 v1(67.7,96.29) ; C102.1 C103.1 56.64,80.81 v1(56.77,80.94) ; v1(54.23,85.45) v1(54.23,84.68) 54.99,84.68 C95.2 54.99,85.45 v1(54.23,85.45) ; C113.1 v1(61.3,84.29) ; R97.1 v1(65.41,83.49)
  vias: v1(20.24,72.11) v1(21.26,72.21) v1(24,72.36) v1(24.64,72.36) v1(51.18,71.09) v1(51.94,71.09) v1(54.74,71.48) v1(55.49,71.46) v1(59.18,71.59) v1(59.94,71.59) v1(60.71,71.59)
AIN0: length 38.7
  TOP w0.121: U5.B6 49.52,87.94 49.52,87.29 49.91,86.89 49.91,85.57 49.26,84.92 49.26,78.79 48.77,78.3 48.77,75.41 48.78,75.4 48.78,75.33 49.72,74.39 56.57,74.39 58.95,72.01 60.96,72.01 61.62,71.35 66.47,71.35 68.07,69.75 68.07,68.3 P9.39
AIN1: length 32
  TOP w0.121: v1(49.52,88.73) U5.C7
  LYR4 w0.133: v1(49.52,88.73) 49.91,88.34 49.91,87.6 51.82,85.7 52.58,85.7 54,84.28 56.16,84.28 58.93,81.51 58.93,75.9 63.6,71.22 67.69,71.22 P9.40
AIN2: length 37.5
  TOP w0.121: U5.B7 48.72,87.94 48.72,87.32 49.35,86.69 49.35,85.78 48.76,85.19 48.76,79.01 48.26,78.51 48.26,75.16 48.29,75.13 48.29,75.13 49.52,73.9 49.52,73.9 49.53,73.89 54.5,73.89 55.27,73.12 55.27,72.25 56.68,70.84 64.68,70.84 65.66,69.87 65.66,68.17 P9.37
AIN3: length 34.2
  TOP w0.121: U5.A7 49.12,87.31 49.6,86.82 49.6,85.64 49.01,85.05 49.01,78.89 48.79,78.67 48.79,78.67 48.51,78.4 48.51,75.41 48.52,75.41 48.52,75.31 48.53,75.3 48.53,75.23 49.62,74.14 54.71,74.14 55.55,73.3 55.55,72.32 56.77,71.09 65.28,71.09 P9.38
AIN4: length 31.1
  TOP w0.121: U5.C8 v1(48.72,88.73)
  LYR4 w0.133: P9.33 62.99,68.3 62.99,71.15 58.55,75.59 58.55,81.45 56.05,83.95 53.93,83.95 52.56,85.32 50.67,85.32 49.53,86.46 49.53,87.92 v1(48.72,88.73)
AIN5: length 36.4
  TOP w0.121: P9.36 63.12,68.43 53.49,68.43 52.7,69.22 52.7,69.77 51.89,70.59 50.65,70.59 50.04,71.2 48.3,71.2 47.43,72.06 47.43,73.14 47.24,73.33 47.24,75.27 47.03,75.48 47.03,78.12 48.26,79.35 48.26,86.97 47.92,87.31 47.92,87.94 U5.B8
AIN6: length 38.5
  TOP w0.121: P9.35 65.21,67.98 65.21,69.96 64.61,70.56 54.66,70.56 53.59,71.63 50.79,71.63 50.67,71.51 48.34,71.51 47.68,72.16 47.68,73.24 47.49,73.43 47.49,75.37 47.28,75.58 47.28,77.91 48.51,79.15 48.51,85.32 49.1,85.91 49.1,86.51 48.32,87.29 U5.A8
AIN7: length 10.4
  TOP w0.121: U5.C9 v1(47.92,88.74)
  LYR4 w0.133: v1(49.66,83.1) 49.63,83.13 49.56,83.13 49.15,83.54 49.15,87.5 v1(47.92,88.73)
  BOTTOM w0.121: R164.1 50.16,80.81 49.97,81 49.97,81.64 49.78,81.83 R163.2 49.34,82.72 49.66,83.03 v1(49.66,83.1)
B_UART0_RX: length 13.5
  TOP w0.121: J1.4 50.57,71.76 48.44,71.76 47.93,72.27 47.93,73.34 47.74,73.53 47.74,75.47 47.75,75.48 R165.1
  BOTTOM w0.121: U15.2 53.33,76.31 53.59,76.05 53.59,74.78 J1.4
B_UART0_TX: length 5.2
  BOTTOM w0.121: J1.5 54.1,73.76 53.85,74.02 53.85,76.3 53.35,76.8 U15.3
